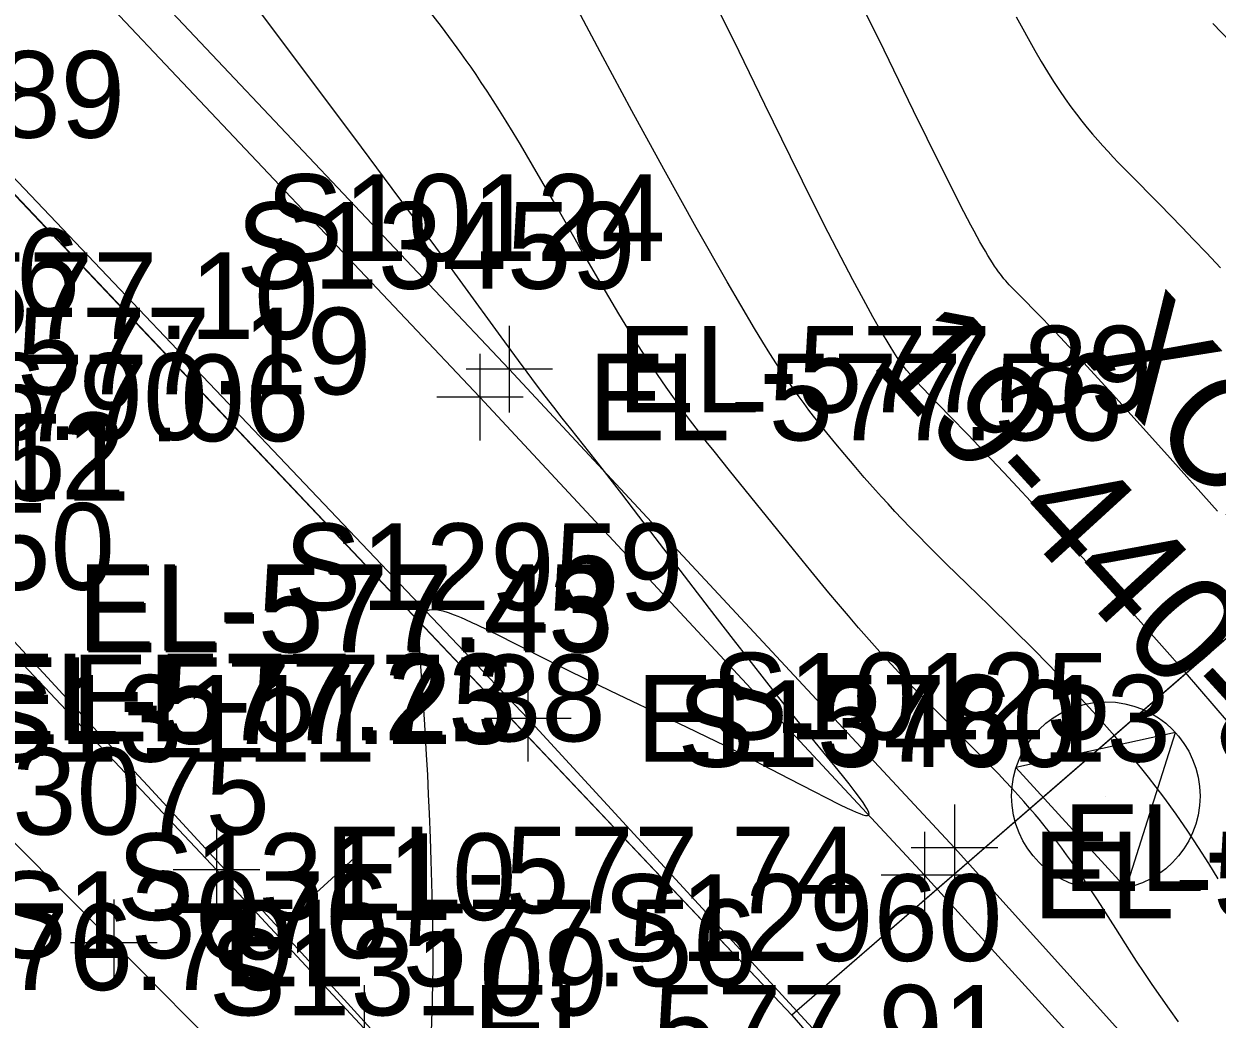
# Model space of a CAD drawing. Extents: x 1729869 to 1735532, y 648588 to 653771.
# Drawn here: x 1731216.8 to 1731271.9, y 652032.5 to 652078.5 of the extents above; entities that cross this region are included whole.
import ezdxf

# ---------------------------------------------------------------- set-up
doc = ezdxf.new("R2010")
doc.units = 0
for name, color, linetype in [('SURVEY - CENTERLINE - Preliminary', 7, 'Continuous'), ('SURVEY - CENTERLINE - Preliminary Text', 7, 'Continuous'), ('SURVEY - CONTOURS - Index with Text', 7, 'Continuous'), ('SURVEY - CONTOURS - Intermediate with optional Text', 7, 'Continuous'), ('SURVEY - CONTROL with Text', 7, 'Continuous'), ('SURVEY - DRAINAGE - Area Shapes', 7, 'Continuous'), ('SURVEY - DRAINAGE - Area Shapes Text', 7, 'Continuous'), ('SURVEY - DTM - Breaklines', 7, 'Continuous'), ('SURVEY - DTM - Breaklines - Points - Elevations', 7, 'Continuous'), ('SURVEY - DTM - Breaklines - Points - Locators', 7, 'Continuous'), ('SURVEY - DTM - Breaklines - Points - Numbers', 7, 'Continuous'), ('SURVEY - TRAFFIC CONTROL - Pavement Marking - Points - Elevations', 7, 'Continuous'), ('SURVEY - TRAFFIC CONTROL - Pavement Marking - Points - Numbers', 7, 'Continuous'), ('SURVEY - TRANSPORTATION - Features', 7, 'Continuous'), ('SURVEY - TRANSPORTATION - Features - Points - Elevations', 7, 'Continuous'), ('SURVEY - TRANSPORTATION - Features - Points - Locators', 7, 'Continuous'), ('SURVEY - TRANSPORTATION - Features - Points - Numbers', 7, 'Continuous'), ('SURVEY - TRANSPORTATION - Roads', 7, 'Continuous'), ('SURVEY - TRANSPORTATION - Roads - Points - Elevations', 7, 'Continuous'), ('SURVEY - TRANSPORTATION - Roads - Points - Locators', 7, 'Continuous'), ('SURVEY - TRANSPORTATION - Roads - Points - Numbers', 7, 'Continuous')]:
    doc.layers.add(name, color=color, linetype=linetype)

msp = doc.modelspace()

# ---------------------------------------------------------------- linework, layer by layer
at = {"layer": 'SURVEY - CENTERLINE - Preliminary'}
msp.add_arc((1729018.342, 650008.232), 3000, 36.727042, 45.05905, dxfattribs=at)
at = {"layer": 'SURVEY - CENTERLINE - Preliminary Text'}
msp.add_line((1731228.565, 652036.756), (1731232.249, 652040.137), dxfattribs=at)
at = {"layer": 'SURVEY - CONTOURS - Index with Text'}
msp.add_lwpolyline([(1731271.959, 652039.016), (1731271.52, 652039.719), (1731271.054, 652040.451), (1731270.556, 652041.21), (1731270.023, 652041.989), (1731269.451, 652042.784), (1731268.745, 652043.711), (1731267.988, 652044.65), (1731267.186, 652045.598), (1731266.344, 652046.551), (1731265.467, 652047.507), (1731264.561, 652048.461), (1731263.504, 652049.539), (1731262.437, 652050.6), (1731261.384, 652051.631), (1731260.366, 652052.621), (1731259.406, 652053.558), (1731258.526, 652054.431), (1731258.118, 652054.843), (1731257.734, 652055.237), (1731257.374, 652055.614), (1731257.035, 652055.974), (1731256.715, 652056.318), (1731256.414, 652056.648), (1731256.137, 652056.957), (1731255.873, 652057.255), (1731255.622, 652057.542), (1731255.151, 652058.09), (1731254.716, 652058.605), (1731254.303, 652059.101), (1731253.895, 652059.6), (1731253.487, 652060.11), (1731253.28, 652060.376), (1731253.066, 652060.655), (1731252.845, 652060.951), (1731252.613, 652061.268), (1731252.369, 652061.611), (1731252.118, 652061.973), (1731251.852, 652062.366), (1731251.568, 652062.796), (1731251.265, 652063.267), (1731250.941, 652063.784), (1731250.549, 652064.424), (1731249.285, 652066.571), (1731247.858, 652069.083), (1731246.363, 652071.776), (1731244.893, 652074.467), (1731243.544, 652076.972), (1731242.408, 652079.105)], dxfattribs=at)
at = {"layer": 'SURVEY - CONTOURS - Intermediate with optional Text'}
for points in [[(1731235.62, 652031.481), (1731235.68, 652033.356), (1731235.702, 652034.261), (1731235.711, 652034.81), (1731235.715, 652035.359), (1731235.715, 652035.636), (1731235.713, 652036.154), (1731235.707, 652036.679), (1731235.697, 652037.211), (1731235.672, 652038.291), (1731235.627, 652039.857), (1731235.593, 652040.891), (1731235.549, 652042.021), (1731235.51, 652042.91), (1731235.465, 652043.816), (1731235.414, 652044.742), (1731235.33, 652046.141), (1731235.241, 652047.522), (1731235.125, 652049.253), (1731235.102, 652049.648), (1731235.094, 652049.837), (1731235.088, 652050.018), (1731235.087, 652050.329), (1731235.101, 652050.612), (1731235.135, 652050.862), (1731235.192, 652051.073), (1731235.277, 652051.241), (1731235.395, 652051.361), (1731235.543, 652051.428), (1731235.721, 652051.451), (1731235.929, 652051.435), (1731236.162, 652051.386), (1731236.418, 652051.307), (1731236.695, 652051.205), (1731236.853, 652051.141), (1731237.016, 652051.071), (1731237.184, 652050.997), (1731237.534, 652050.837), (1731237.715, 652050.752), (1731238.255, 652050.491), (1731238.82, 652050.212), (1731239.4, 652049.922), (1731241.222, 652049.002), (1731241.967, 652048.631), (1731242.69, 652048.276), (1731243.4, 652047.932), (1731244.266, 652047.52), (1731246.463, 652046.48), (1731247.4, 652046.031), (1731248.354, 652045.567), (1731249.179, 652045.159), (1731250.22, 652044.636), (1731250.928, 652044.274), (1731252.138, 652043.647), (1731253.305, 652043.042), (1731253.847, 652042.764), (1731254.475, 652042.448), (1731254.832, 652042.274), (1731255.048, 652042.174), (1731255.242, 652042.088), (1731255.414, 652042.019), (1731255.56, 652041.968), (1731255.679, 652041.939), (1731255.767, 652041.934), (1731255.821, 652041.956), (1731255.841, 652042.001), (1731255.832, 652042.068), (1731255.799, 652042.156), (1731255.743, 652042.263), (1731255.666, 652042.387), (1731255.572, 652042.527), (1731255.402, 652042.764), (1731255.201, 652043.029), (1731254.921, 652043.388), (1731254.61, 652043.778), (1731254.276, 652044.191), (1731252.786, 652046.011), (1731252.172, 652046.769), (1731251.683, 652047.379), (1731251.118, 652048.091), (1731250.301, 652049.133), (1731249.582, 652050.061), (1731248.482, 652051.493), (1731245.22, 652055.759), (1731244.43, 652056.785), (1731243.893, 652057.477), (1731243.622, 652057.823), (1731243.239, 652058.31), (1731242.068, 652059.79), (1731241.68, 652060.284), (1731241.286, 652060.789), (1731240.889, 652061.302), (1731240.492, 652061.822), (1731240.051, 652062.408), (1731239.656, 652062.943), (1731238.858, 652064.036), (1731237.085, 652066.474), (1731236.145, 652067.759), (1731235.225, 652069.007), (1731233.831, 652070.886), (1731232.055, 652073.267), (1731225.168, 652082.472)], [(1731271.923, 652055.987), (1731269.477, 652058.72), (1731267.226, 652061.218), (1731265.242, 652063.393), (1731264.677, 652064.003), (1731264.196, 652064.515), (1731263.791, 652064.94), (1731263.451, 652065.29), (1731263.05, 652065.693), (1731262.552, 652066.186), (1731262.386, 652066.356), (1731262.305, 652066.442), (1731262.225, 652066.531), (1731262.147, 652066.62), (1731262.068, 652066.715), (1731261.987, 652066.816), (1731261.903, 652066.925), (1731261.816, 652067.043), (1731261.725, 652067.171), (1731261.633, 652067.307), (1731261.536, 652067.456), (1731261.433, 652067.618), (1731261.324, 652067.795), (1731261.209, 652067.987), (1731261.086, 652068.197), (1731260.961, 652068.419), (1731260.827, 652068.658), (1731260.686, 652068.916), (1731260.538, 652069.193), (1731260.381, 652069.489), (1731260.216, 652069.806), (1731259.152, 652071.916), (1731257.899, 652074.472), (1731256.533, 652077.275), (1731255.13, 652080.131)], [(1731272.439, 652046.232), (1731270.447, 652048.531), (1731268.266, 652050.993), (1731266.044, 652053.458), (1731263.929, 652055.77), (1731262.067, 652057.77), (1731261.462, 652058.41), (1731260.912, 652058.986), (1731260.415, 652059.504), (1731259.57, 652060.375), (1731258.641, 652061.33), (1731258.303, 652061.683), (1731258.027, 652061.979), (1731257.864, 652062.16), (1731257.717, 652062.331), (1731257.575, 652062.504), (1731257.434, 652062.685), (1731257.293, 652062.877), (1731257.144, 652063.089), (1731256.984, 652063.33), (1731256.813, 652063.6), (1731256.625, 652063.908), (1731256.402, 652064.286), (1731256.02, 652064.957), (1731255.581, 652065.753), (1731255.089, 652066.67), (1731254.547, 652067.703), (1731253.958, 652068.847), (1731253.327, 652070.097), (1731252.208, 652072.354), (1731251.029, 652074.764), (1731249.838, 652077.207), (1731248.68, 652079.562)], [(1731270.129, 652032.405), (1731269.713, 652032.983), (1731269.308, 652033.556), (1731268.914, 652034.125), (1731268.533, 652034.689), (1731268.192, 652035.207), (1731267.861, 652035.718), (1731267.229, 652036.714), (1731266.626, 652037.662), (1731266.381, 652038.042), (1731266.139, 652038.412), (1731265.899, 652038.773), (1731265.661, 652039.126), (1731265.423, 652039.47), (1731265.185, 652039.808), (1731264.962, 652040.119), (1731264.736, 652040.426), (1731264.507, 652040.731), (1731264.273, 652041.035), (1731264.033, 652041.339), (1731263.692, 652041.757), (1731263.502, 652041.983), (1731263.252, 652042.276), (1731262.99, 652042.575), (1731262.716, 652042.881), (1731262.429, 652043.196), (1731262.127, 652043.521), (1731261.809, 652043.856), (1731261.14, 652044.546), (1731260.423, 652045.271), (1731258.907, 652046.796), (1731258.141, 652047.577), (1731257.39, 652048.359), (1731256.858, 652048.929), (1731256.341, 652049.493), (1731255.841, 652050.052), (1731255.355, 652050.605), (1731254.884, 652051.152), (1731254.426, 652051.691), (1731253.991, 652052.21), (1731253.568, 652052.721), (1731253.155, 652053.225), (1731252.352, 652054.213), (1731249.397, 652057.868), (1731249.043, 652058.308), (1731248.687, 652058.754), (1731248.328, 652059.21), (1731247.965, 652059.678), (1731247.596, 652060.162), (1731247.229, 652060.654), (1731246.854, 652061.169), (1731246.468, 652061.714), (1731246.07, 652062.294), (1731245.657, 652062.914), (1731245.174, 652063.666), (1731244.289, 652065.104), (1731243.362, 652066.67), (1731242.417, 652068.299), (1731241.482, 652069.925), (1731240.583, 652071.484), (1731239.745, 652072.91), (1731239.407, 652073.472), (1731239.085, 652073.997), (1731238.778, 652074.49), (1731238.486, 652074.951), (1731238.207, 652075.381), (1731237.941, 652075.784), (1731237.698, 652076.144), (1731237.466, 652076.483), (1731237.244, 652076.801), (1731237.031, 652077.101), (1731236.826, 652077.385), (1731236.445, 652077.901), (1731236.096, 652078.366), (1731235.448, 652079.212)], [(1731262.636, 652078.811), (1731263.495, 652077.258), (1731263.793, 652076.747), (1731264.082, 652076.271), (1731264.362, 652075.826), (1731264.634, 652075.412), (1731264.898, 652075.024), (1731265.156, 652074.663), (1731265.414, 652074.315), (1731265.666, 652073.989), (1731265.913, 652073.683), (1731266.156, 652073.393), (1731266.395, 652073.118), (1731266.631, 652072.855), (1731266.871, 652072.593), (1731267.109, 652072.339), (1731267.346, 652072.091), (1731267.816, 652071.61), (1731269.258, 652070.153), (1731269.759, 652069.643), (1731270.28, 652069.104), (1731270.824, 652068.535), (1731271.411, 652067.913), (1731272.058, 652067.218)], [(1731271.709, 652078.51), (1731272.525, 652077.655)]]:
    msp.add_lwpolyline(points, dxfattribs=at)
at = {"layer": 'SURVEY - CONTROL with Text'}
for p, q in [((1731269.98, 652045.77), (1731262.623, 652044.143)), ((1731267.71, 652038.585), (1731269.98, 652045.77)), ((1731262.623, 652044.143), (1731267.71, 652038.585)), ((1731266.771, 652042.833), (1731266.771, 652042.833))]:
    msp.add_line(p, q, dxfattribs=at)
msp.add_circle((1731266.771, 652042.833), 4.35, dxfattribs=at)
at = {"layer": 'SURVEY - DRAINAGE - Area Shapes'}
for points in [[(1731097.142, 652171.409), (1731011.148, 652256.97), (1730865.03, 652403.158), (1730749.606, 652518.939), (1730781.764, 652550.883), (1730851.291, 652571.58), (1730949.072, 652515.98), (1730982.838, 652438.563), (1731020.351, 652368.14), (1731165.291, 652192.393), (1731281.807, 652137.032), (1731316.797, 652088.672), (1731252.279, 652032.718), (1731179.777, 652109.245)], [(1731447.67, 651794.75), (1731494.62, 651848.132), (1731494.044, 651850.166), (1731316.797, 652088.672), (1731252.279, 652032.718), (1731331.927, 651940.868), (1731377.361, 651886.729)]]:
    msp.add_lwpolyline(points, close=True, dxfattribs=at)
at = {"layer": 'SURVEY - DRAINAGE - Area Shapes Text'}
msp.add_lwpolyline([(1731252.279, 652032.718), (1731252.279, 652032.718), (1731331.927, 651940.868), (1731382.756, 651879.672), (1731447.67, 651794.75), (1731482.093, 651747.619), (1731463.009, 651708.574), (1731417.334, 651769.604), (1731372.727, 651826.43), (1731331.142, 651879.707), (1731270.184, 651948.802), (1731219.221, 652002.428), (1731149.8, 652071.308), (1731071.45, 652144.137), (1731094.843, 652173.647), (1731097.142, 652171.409), (1731179.777, 652109.245)], close=True, dxfattribs=at)
at = {"layer": 'SURVEY - DTM - Breaklines'}
msp.add_lwpolyline([(1731035.462, 652269.556), (1731036.254, 652268.75), (1731049.78, 652255.258), (1731071.01, 652234.055), (1731092.233, 652212.831), (1731113.392, 652191.515), (1731134.61, 652170.281), (1731155.653, 652148.89), (1731176.704, 652127.515), (1731197.722, 652105.922), (1731218.638, 652084.352), (1731239.234, 652062.543), (1731259.779, 652040.444), (1731279.977, 652018.028), (1731278.681, 652016.879)], dxfattribs=at)
at = {"layer": 'SURVEY - DTM - Breaklines - Points - Locators'}
for p, q in [((1731239.234, 652064.543), (1731239.234, 652060.543)), ((1731241.234, 652062.543), (1731237.234, 652062.543)), ((1731259.779, 652042.444), (1731259.779, 652038.444)), ((1731261.779, 652040.444), (1731257.779, 652040.444))]:
    msp.add_line(p, q, dxfattribs=at)
at = {"layer": 'SURVEY - TRANSPORTATION - Features'}
msp.add_lwpolyline([(1731033.434, 652270.024), (1731034.936, 652267.426), (1731048.46, 652253.936), (1731069.689, 652232.733), (1731090.91, 652211.511), (1731112.063, 652190.199), (1731133.28, 652168.968), (1731154.322, 652147.578), (1731175.372, 652126.204), (1731196.374, 652104.628), (1731217.283, 652083.065), (1731237.88, 652061.256), (1731258.402, 652039.18), (1731278.681, 652016.879)], dxfattribs=at)
at = {"layer": 'SURVEY - TRANSPORTATION - Features - Points - Locators'}
for p, q in [((1731237.88, 652063.256), (1731237.88, 652059.256)), ((1731239.88, 652061.256), (1731235.88, 652061.256)), ((1731258.402, 652041.18), (1731258.402, 652037.18)), ((1731260.402, 652039.18), (1731256.402, 652039.18))]:
    msp.add_line(p, q, dxfattribs=at)
at = {"layer": 'SURVEY - TRANSPORTATION - Roads'}
for points in [[(1731283.394, 651975.645), (1731259.51, 652002.579), (1731252.817, 652010.007), (1731242.05, 652021.841), (1731236.611, 652027.706), (1731232.532, 652032.105), (1731225.713, 652039.419), (1731214.299, 652051.538), (1731203.18, 652063.38), (1731191.811, 652075.231), (1731177.736, 652089.726), (1731158.199, 652109.78), (1731151.218, 652116.94), (1731121.781, 652146.893), (1731097.861, 652171.053), (1731071.042, 652197.973)], [(1731092.244, 652198.318), (1731110.548, 652179.854), (1731142.862, 652147.122), (1731152.688, 652137.151), (1731159.703, 652130.027), (1731177.944, 652111.504), (1731189.048, 652099.987), (1731201.505, 652086.997), (1731205.657, 652082.667), (1731240.089, 652046.42), (1731254.968, 652030.216), (1731269.804, 652013.975), (1731291.041, 651990.04)], [(1731072.201, 652175.531), (1731076.714, 652171.579), (1731085.681, 652163.606), (1731099.12, 652151.634), (1731106.542, 652144.934), (1731109.511, 652142.254), (1731121.387, 652131.536), (1731125.84, 652127.515), (1731143.434, 652111.195), (1731150.728, 652104.355), (1731159.448, 652096.114), (1731173.982, 652082.379), (1731189.738, 652067.029), (1731209.701, 652047.399), (1731220.979, 652036.052), (1731226.59, 652030.351), (1731240.437, 652015.923), (1731244.586, 652011.589), (1731251.47, 652004.337), (1731256.919, 651998.481), (1731269.179, 651985.304)]]:
    msp.add_lwpolyline(points, dxfattribs=at)
at = {"layer": 'SURVEY - TRANSPORTATION - Roads - Points - Locators'}
for p, q in [((1731240.089, 652048.42), (1731240.089, 652044.42)), ((1731242.089, 652046.42), (1731238.089, 652046.42)), ((1731225.713, 652041.419), (1731225.713, 652037.419)), ((1731227.713, 652039.419), (1731223.713, 652039.419)), ((1731220.979, 652038.052), (1731220.979, 652034.052)), ((1731222.979, 652036.052), (1731218.979, 652036.052)), ((1731232.532, 652034.105), (1731232.532, 652030.105))]:
    msp.add_line(p, q, dxfattribs=at)

# ---------------------------------------------------------------- texts
at = {"layer": 'SURVEY - CONTROL with Text'}
for s, p in [('XCP-S32', (1731265.649, 652063.09)), ('19-440-32', (1731255.813, 652062.84))]:
    msp.add_text(s, height=5, rotation=312.4661, dxfattribs=at).set_placement(p)
at = {"layer": 'SURVEY - DTM - Breaklines - Points - Elevations'}
for s, p in [('EL-577.89', (1731244.234, 652060.543)), ('EL-578.39', (1731264.779, 652038.444))]:
    msp.add_text(s, height=4, dxfattribs=at).set_placement(p)
at = {"layer": 'SURVEY - DTM - Breaklines - Points - Numbers'}
for s, p in [('S10124', (1731227.994, 652067.543)), ('S10125', (1731248.539, 652045.444))]:
    msp.add_text(s, height=4, dxfattribs=at).set_placement(p)
at = {"layer": 'SURVEY - TRAFFIC CONTROL - Pavement Marking - Points - Elevations'}
for s, p in [('EL-577.10', (1731205.75, 652063.937)), ('EL-576.90', (1731200.621, 652059.28)), ('EL-577.06', (1731205.318, 652059.216)), ('EL-577.43', (1731219.366, 652049.467)), ('EL-577.25', (1731214.863, 652045.239)), ('EL-577.38', (1731219.001, 652045.358))]:
    msp.add_text(s, height=4, dxfattribs=at).set_placement(p)
at = {"layer": 'SURVEY - TRAFFIC CONTROL - Pavement Marking - Points - Numbers'}
for s, p in [('S11951', (1731203.284, 652056.467)), ('S11950', (1731202.588, 652052.358))]:
    msp.add_text(s, height=4, dxfattribs=at).set_placement(p)
at = {"layer": 'SURVEY - TRANSPORTATION - Features - Points - Elevations'}
for s, p in [('EL-577.56', (1731242.88, 652059.256)), ('EL-578.06', (1731263.402, 652037.18))]:
    msp.add_text(s, height=4, dxfattribs=at).set_placement(p)
at = {"layer": 'SURVEY - TRANSPORTATION - Features - Points - Numbers'}
for s, p in [('S13459', (1731226.625, 652066.256)), ('S13460', (1731246.989, 652044.18))]:
    msp.add_text(s, height=4, dxfattribs=at).set_placement(p)
at = {"layer": 'SURVEY - TRANSPORTATION - Roads - Points - Elevations'}
for s, p in [('EL-576.89', (1731196.811, 652073.231)), ('EL-576.76', (1731194.738, 652065.029)), ('EL-577.19', (1731208.18, 652061.38)), ('EL-577.45', (1731219.299, 652049.538)), ('EL-577.23', (1731214.701, 652045.399)), ('EL-578.13', (1731245.089, 652044.42)), ('EL-577.74', (1731230.713, 652037.419)), ('EL-577.56', (1731225.979, 652034.052)), ('EL-576.79', (1731204.624, 652033.873)), ('EL-577.91', (1731237.532, 652030.105))]:
    msp.add_text(s, height=4, dxfattribs=at).set_placement(p)
at = {"layer": 'SURVEY - TRANSPORTATION - Roads - Points - Numbers'}
for s, p in [('S13112', (1731203.059, 652056.538)), ('S12959', (1731228.834, 652051.42)), ('S13111', (1731214.631, 652044.419)), ('S13075', (1731209.739, 652041.052)), ('S13110', (1731221.119, 652037.105)), ('S13076', (1731215.24, 652035.351)), ('S12960', (1731243.555, 652035.216)), ('S13109', (1731225.356, 652032.706))]:
    msp.add_text(s, height=4, dxfattribs=at).set_placement(p)

doc.saveas('drawing.dxf')
